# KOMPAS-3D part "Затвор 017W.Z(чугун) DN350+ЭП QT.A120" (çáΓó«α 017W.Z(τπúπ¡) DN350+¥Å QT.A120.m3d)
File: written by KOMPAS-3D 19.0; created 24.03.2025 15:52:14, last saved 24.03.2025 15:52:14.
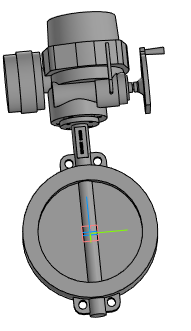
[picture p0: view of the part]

Document properties: Полное имя файла: Затвор 017W.Z(чугун) DN350+ЭП QT.A120.a3d

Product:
- Part/product: Затвор 017W.Z(чугун) DN350+ЭП QT.A120
    Масса: 197.509

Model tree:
1. Операция без истории:1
